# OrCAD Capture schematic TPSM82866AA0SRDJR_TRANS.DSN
size D; title: TPSM82866AA0SRDJR 2.4-V to 5.5-V Input, 6-A Step-Down; rev: 1.1; note: Datasheet: SLUSEF1           EVM: SLVUCB0
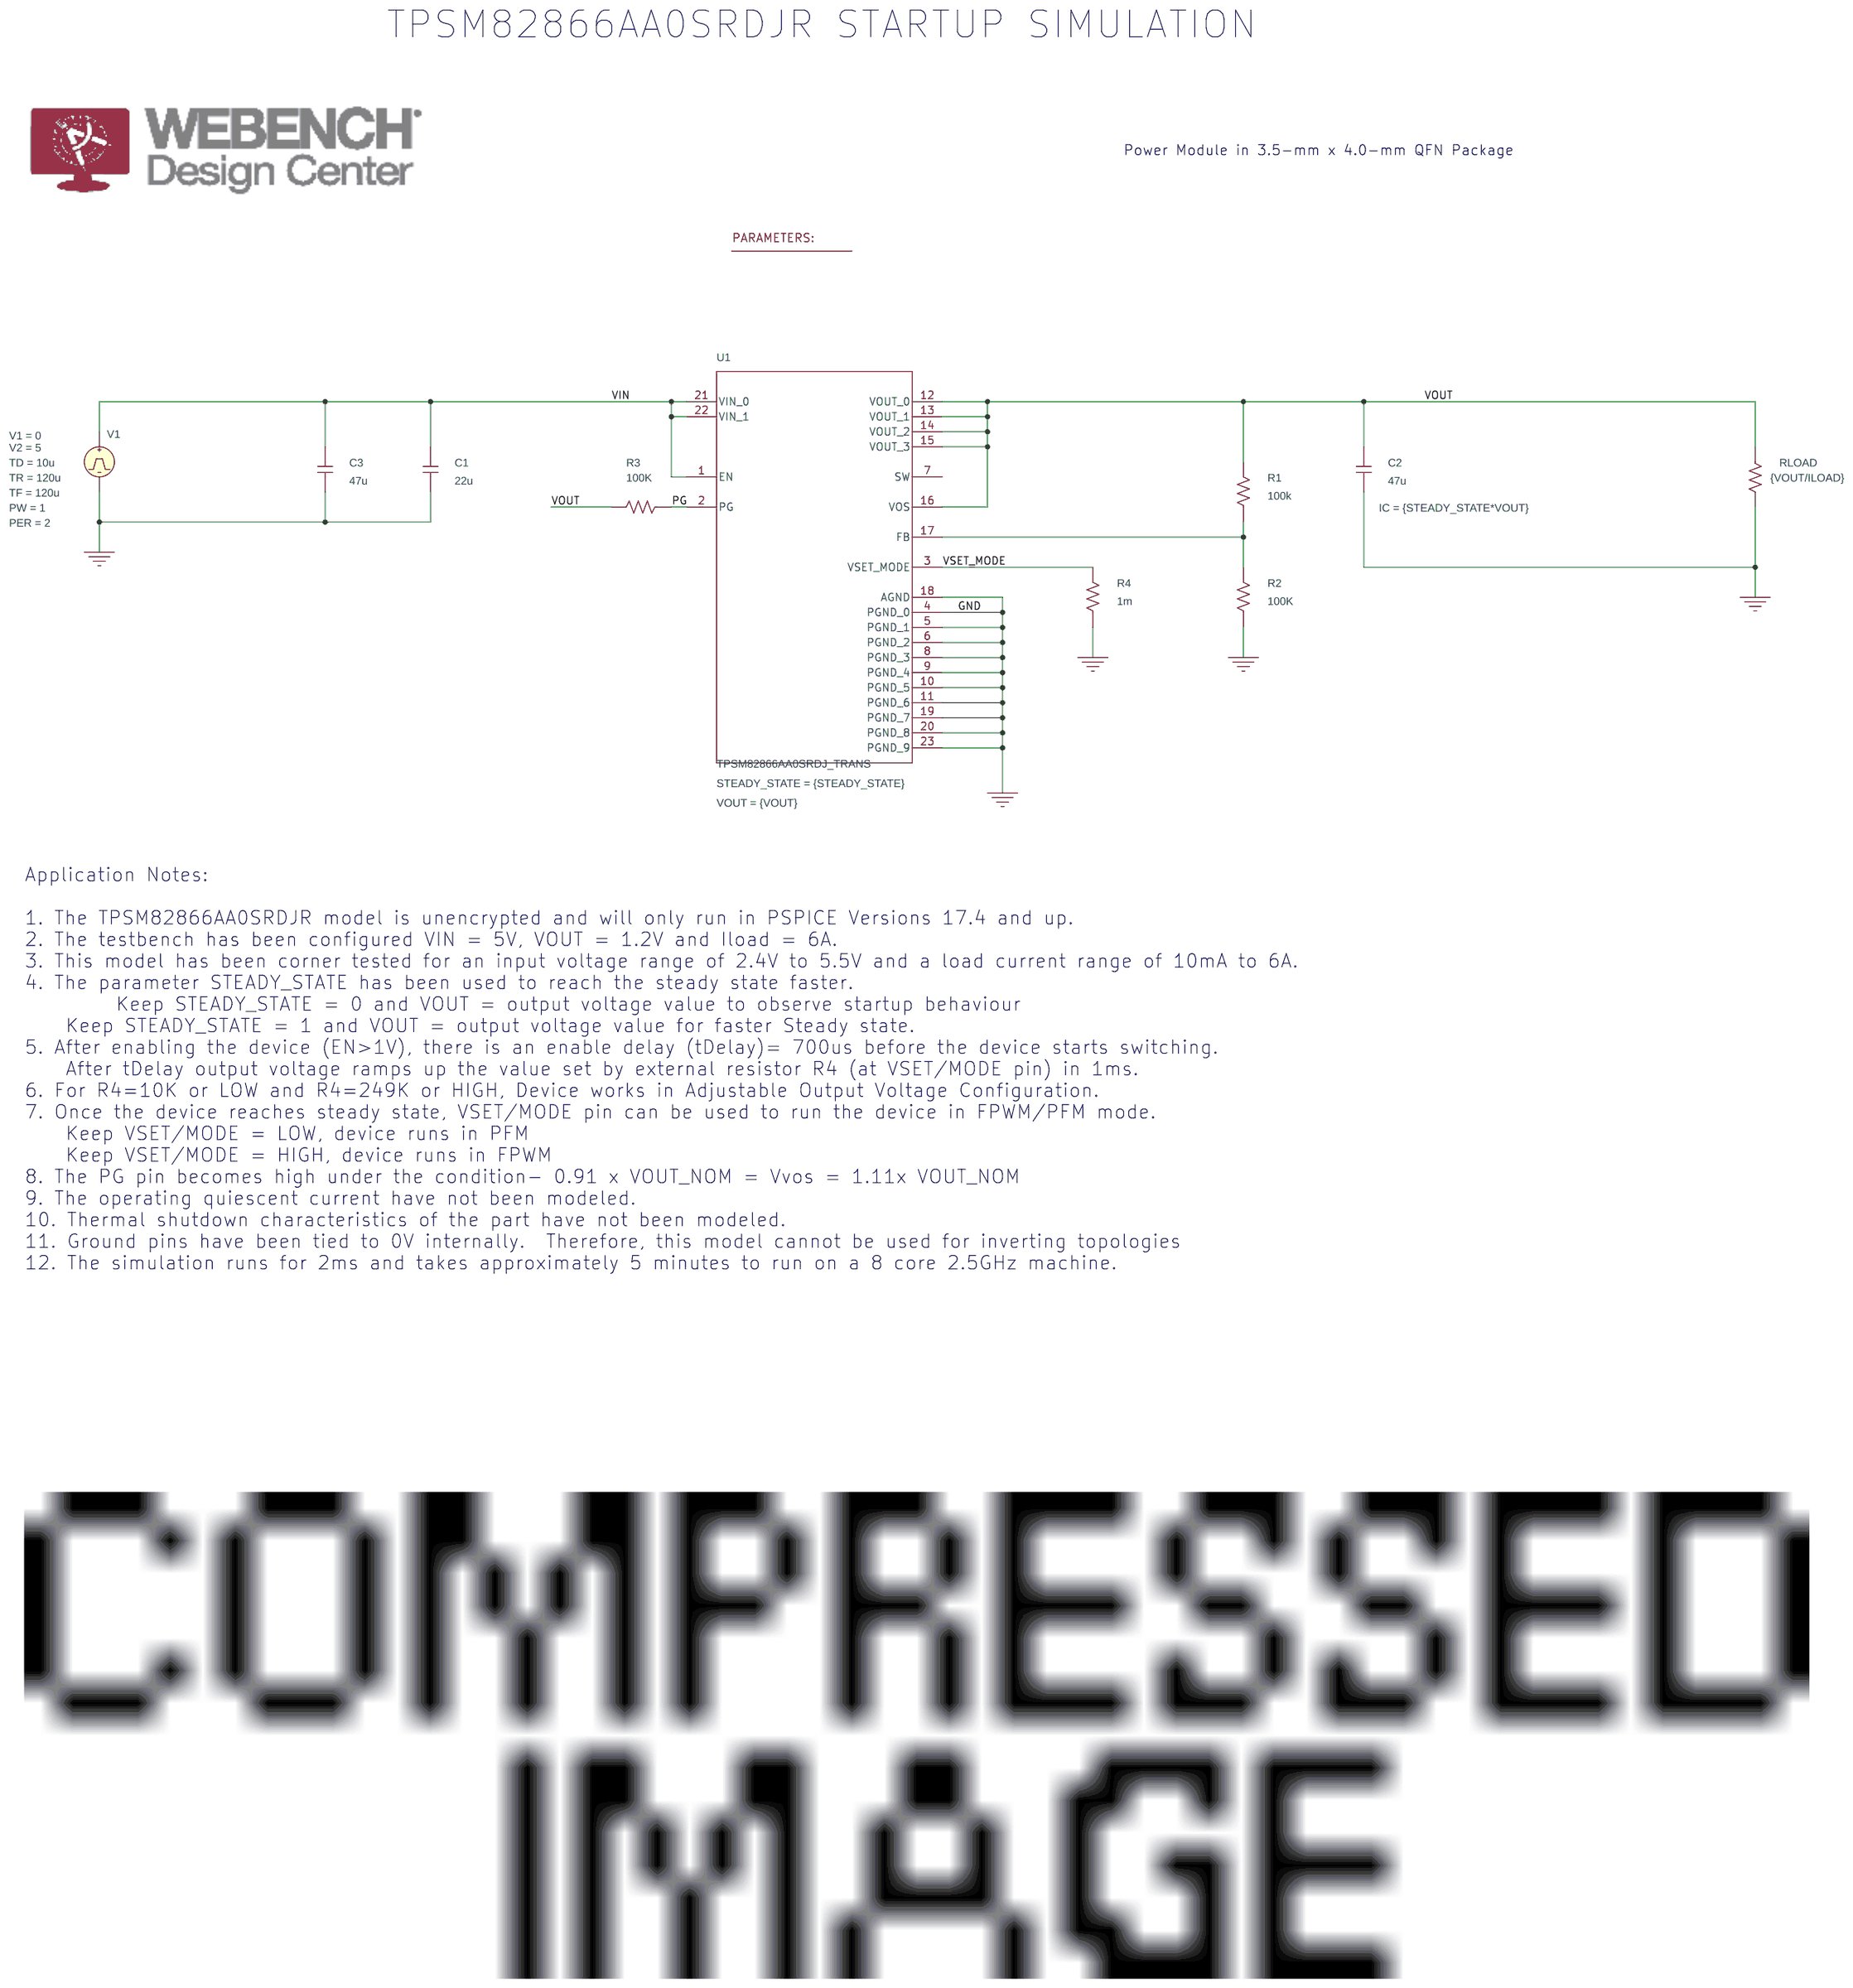
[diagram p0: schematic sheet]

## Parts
5  PARAM
C1  22u  [RAD/CK05]
C2  47u  [RAD/CK05]
C3  47u  [RAD/CK05]
R1  100k  [AX/RC05]
R2  100K  [AX/RC05]
R3  100K  [AX/RC05]
R4  1m  [AX/RC05]
RLOAD  {VOUT/ILOAD}  [AX/RC05]
U1  TPSM82866AA0SRDJ_TRANS  [RDJ0023A-MFG]
V1  VPULSE

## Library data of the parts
5 = PARAM: ILOAD: 6; STEADY_STATE: 0; VOUT: 1.2
C1 C3 = C
C2 = C: IC: {STEADY_STATE*VOUT}
R1-R4 RLOAD = R
U1 = TPSM82866AA0SRDJ_TRANS: STEADY_STATE: {STEADY_STATE}; VOUT: {VOUT}
V1 = VPULSE: PER: 2; PW: 1; TD: 10u; TF: 120u; TR: 120u; V1: 0; V2: 5

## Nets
VIN: C1.2 C3.2 U1.1(EN) U1.21(VIN_0) U1.22(VIN_1) V1.1(+)
0: C1.1 C2.2 C3.1 R2.1 R4.1 RLOAD.2 U1.4(PGND_0) U1.5(PGND_1) U1.6(PGND_2) U1.8(PGND_3) U1.9(PGND_4) U1.10(PGND_5) U1.11(PGND_6) U1.18(AGND) U1.19(PGND_7) U1.20(PGND_8) U1.23(PGND_9) V1.2(-)
PG: R3.1 U1.2(PG)
VOUT: C2.1 R1.2 R3.2 RLOAD.1 U1.12(VOUT_0) U1.13(VOUT_1) U1.14(VOUT_2) U1.15(VOUT_3) U1.16(VOS)
VSET_MODE: R4.2 U1.3(VSET_MODE)
N16508814: R1.1 R2.2 U1.17(FB)

Not connected (* = marked no-connect by the designer): U1 7(SW)

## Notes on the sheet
- TPSM82866AA0SRDJR STARTUP SIMULATION
- Power Module in 3.5-mm x 4.0-mm QFN Package
- Application Notes:
  1. The TPSM82866AA0SRDJR model is unencrypted and will only run in PSPICE Versions 17.4 and up.
  2. The testbench has been configured VIN = 5V, VOUT = 1.2V and Iload = 6A.
  3. This model has been corner tested for an input voltage range of 2.4V to 5.5V and a load current range of 10mA to 6A.
  4. The parameter STEADY_STATE has been used to reach the steady state faster.
  	    Keep STEADY_STATE = 0 and VOUT = output voltage value to observe startup behaviour
      Keep STEADY_STATE = 1 and VOUT = output voltage value for faster Steady state.
  5. After enabling the device (EN>1V), there is an enable delay (tDelay)= 700us before the device starts switching.
      After tDelay output voltage ramps up the value set by external resistor R4 (at VSET/MODE pin) in 1ms.
  6. For R4=10K or LOW and R4=249K or HIGH, Device works in Adjustable Output Voltage Configuration.
  7. Once the device reaches steady state, VSET/MODE pin can be used to run the device in FPWM/PFM mode.
      Keep VSET/MODE = LOW, device runs in PFM
      Keep VSET/MODE = HIGH, device runs in FPWM
  8. The PG pin becomes high under the condition- 0.91 x VOUT_NOM = Vvos = 1.11x VOUT_NOM
  9. The operating quiescent current have not been modeled.
  10. Thermal shutdown characteristics of the part have not been modeled.
  11. Ground pins have been tied to 0V internally.  Therefore, this model cannot be used for inverting topologies
  12. The simulation runs for 2ms and takes approximately 5 minutes to run on a 8 core 2.5GHz machine.
